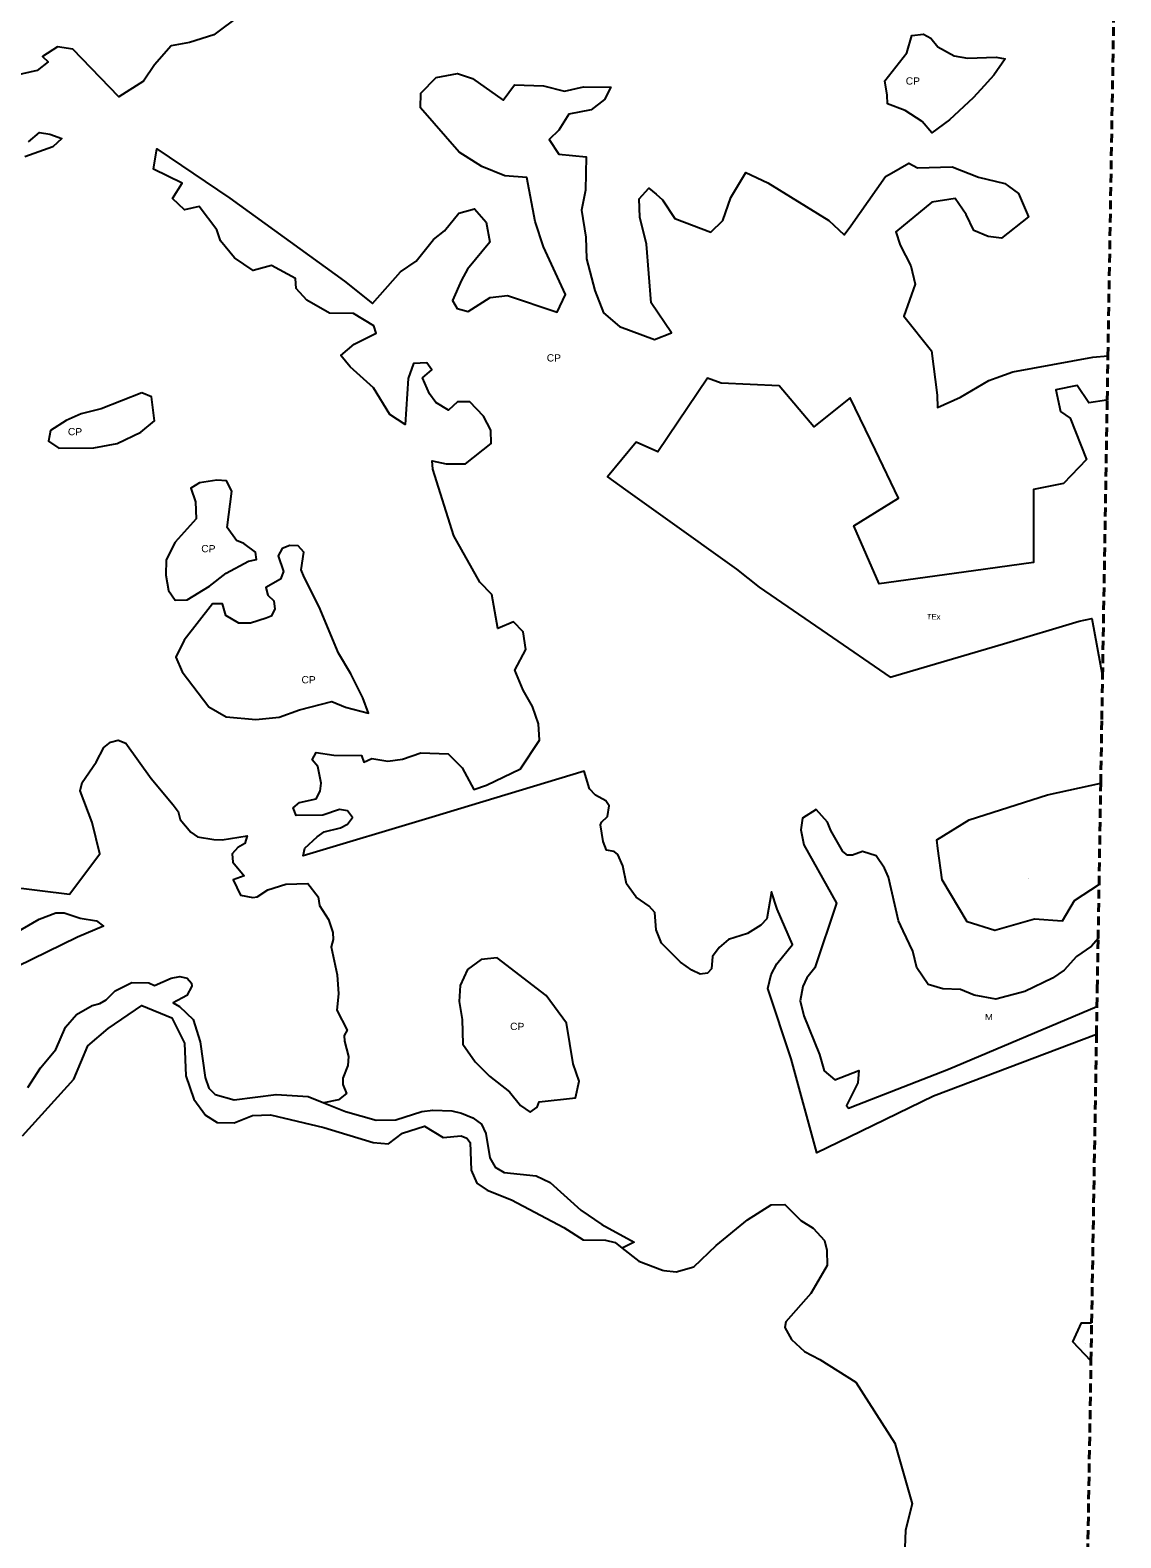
# Model space of a CAD drawing. Extents: x 713589 to 726391, y 7177764 to 7191819.
# Drawn here: x 725333 to 726289, y 7183880 to 7185202 of the extents above; entities that cross this region are included whole.
import ezdxf
from ezdxf.enums import TextEntityAlignment as Align

# ---------------------------------------------------------------- set-up
doc = ezdxf.new("R2010")
doc.units = 0
doc.header["$LTSCALE"] = 2.6
doc.linetypes.add('MEDIUM_DASHED', pattern=[4.5, 3, -1.5])
doc.layers.add('63', color=7, linetype='Continuous', lineweight=25)

msp = doc.modelspace()

# ---------------------------------------------------------------- linework, layer by layer
at = {"layer": '63', "linetype": 'MEDIUM_DASHED', "lineweight": 40}
for p, q in [((726277.23, 7184877.85), (726277.88, 7184916.55)), ((726273.14, 7184635.37), (726277.23, 7184877.85)), ((726270.06, 7184452.88), (726271.56, 7184541.89)), ((726269.26, 7184405.47), (726270.06, 7184452.88)), ((726267.84, 7184321.48), (726268.25, 7184346.03))]:
    msp.add_line(p, q, dxfattribs=at)
for points in [[(726277.88, 7184916.55), (726283.75, 7185264.1), (726286.04, 7185399.94), (726289.19, 7185586.4)], [(726271.56, 7184541.89), (726272.5, 7184597.61), (726273.14, 7184635.37)], [(726268.25, 7184346.03), (726268.51, 7184361.39), (726269.26, 7184405.47)], [(726263.01, 7184035.16), (726263.57, 7184068.5), (726267.84, 7184321.48)], [(726253.89, 7183494.95), (726256.31, 7183638.27), (726259.78, 7183843.69), (726263.01, 7184035.16)]]:
    msp.add_lwpolyline(points, dxfattribs=at)
at = {"layer": '63'}
for points in [[(725516.76, 7185215.41), (725493.64, 7185198.24), (725472.5, 7185191.64), (725456.32, 7185188.67), (725441.78, 7185171.84), (725432.2, 7185157.64), (725410.4, 7185143.77), (725370.12, 7185185.72), (725356.58, 7185187.71), (725343.48, 7185179.22), (725348.33, 7185174.58), (725338.7, 7185166.83), (725319.37, 7185162.58)], [(725718.19, 7184876.27), (725707.39, 7184876.27), (725699.52, 7184869.07), (725688.39, 7184875.62), (725682.83, 7184883.48), (725676.61, 7184897.24), (725684.8, 7184904.44), (725680.54, 7184910.66), (725668.75, 7184910.01), (725664.16, 7184896.91), (725661.53, 7184856.3), (725648.11, 7184865.15), (725633.7, 7184888.73), (725613.4, 7184907.08), (725605.22, 7184916.9), (725616.68, 7184927.05), (725636.01, 7184936.54), (725634.04, 7184943.1), (725616.36, 7184953.91), (725595.07, 7184954.24), (725575.43, 7184965.38), (725565.93, 7184975.86), (725565.28, 7184984.37), (725544.32, 7184995.84), (725528.27, 7184991.59), (725511.9, 7185002.72), (725499.46, 7185017.46), (725496.52, 7185027.29), (725480.8, 7185047.6), (725468.03, 7185044.65), (725457.55, 7185054.81), (725466.07, 7185068.23), (725440.85, 7185080.35), (725443.84, 7185098.36), (725507.7, 7185054.88), (725608.22, 7184982.16), (725633.01, 7184962.46), (725657.39, 7184990.29), (725671.27, 7184999.86), (725686.46, 7185018.68), (725696.04, 7185026.27), (725708.59, 7185041.79), (725722.46, 7185045.75), (725732.7, 7185033.86), (725735.67, 7185016.36), (725716.18, 7184992.58), (725710.89, 7184983.01), (725702.96, 7184965.18), (725707.25, 7184958.24), (725716.83, 7184955.6), (725735.99, 7184967.81), (725751.18, 7184969.46), (725794.77, 7184954.92), (725802.04, 7184970.44), (725782.89, 7185012.39), (725775.63, 7185034.51), (725768.37, 7185073.15), (725748.89, 7185074.48), (725728.75, 7185082.74), (725708.93, 7185095.29), (725674.93, 7185134.27), (725675.26, 7185147.15), (725688.8, 7185160.69), (725707.3, 7185164.31), (725720.51, 7185160.02), (725747.58, 7185140.86), (725757.49, 7185154.4), (725782.92, 7185153.4), (725801.41, 7185148.77), (725817.93, 7185152.73), (725842.04, 7185152.4), (725836.42, 7185141.5), (725824.53, 7185132.59), (725805.04, 7185128.63), (725796.45, 7185114.76), (725787.87, 7185106.5), (725796.45, 7185093.62), (725820.23, 7185091.31), (725819.56, 7185061.91), (725816.25, 7185044.41), (725819.88, 7185020.63), (725820.54, 7185001.81), (725827.8, 7184974.07), (725835.39, 7184954.25), (725849.59, 7184942.36), (725880.3, 7184931.12), (725895.16, 7184936.73), (725877.33, 7184963.16), (725873.05, 7185014.68), (725867.44, 7185038.46), (725866.88, 7185054.27), (725875.37, 7185063.88), (725881.6, 7185058.51), (725887.26, 7185053.64)], [(725331.15, 7185104.28), (725340.98, 7185112.47), (725349.82, 7185111.16), (725360.3, 7185107.23), (725352.44, 7185100.02), (725327.87, 7185091.19)], [(725887.26, 7185053.64), (725898.15, 7185037.13), (725929.52, 7185025.23), (725940.09, 7185035.47), (725947.03, 7185055.61), (725949.64, 7185059.91), (725960.25, 7185077.41), (725979.73, 7185068.48), (726033.22, 7185035.45), (726041.9, 7185027.2), (726046.43, 7185022.9), (726052.46, 7185030.76), (726082.84, 7185074.06), (726087.92, 7185076.94), (726103.25, 7185085.63), (726110.84, 7185081.67), (726141.22, 7185082.32), (726164.34, 7185073.4), (726187.45, 7185067.78), (726190.71, 7185065.43), (726199.34, 7185059.19), (726208.25, 7185038.71), (726184.47, 7185019.89), (726172.91, 7185021.22), (726160.37, 7185026.5), (726153.43, 7185040.71), (726143.86, 7185054.58), (726123.38, 7185051.61), (726091.72, 7185025.43), (726095.63, 7185013.84), (726104.88, 7184995.67), (726108.84, 7184979.49), (726098.92, 7184951.42), (726123.03, 7184921.03), (726127.97, 7184882.06), (726128.46, 7184871.32), (726148.45, 7184880.54), (726173.55, 7184895.06), (726179.94, 7184897.39), (726194.35, 7184902.65), (726264.51, 7184915.55), (726277.88, 7184916.55)], [(726277.23, 7184877.85), (726276.6, 7184877.76), (726261.15, 7184875.38), (726250.82, 7184890.67), (726232.21, 7184886.85), (726236.34, 7184867.74), (726244.61, 7184862), (726259.09, 7184825.7), (726238.99, 7184804.7), (726212.59, 7184799.48), (726212.66, 7184735.42), (726160.1, 7184728.12), (726077.24, 7184716.62), (726055.1, 7184767.57), (726094.33, 7184791.76), (726073.97, 7184834.03), (726051.91, 7184879.85), (726019.89, 7184854.49), (725989.41, 7184890.38), (725938.66, 7184892.56), (725926.63, 7184897.01), (725883.08, 7184832.57), (725864.13, 7184840.9), (725838.98, 7184810.68), (725854.78, 7184799.04), (725889.66, 7184774.28), (725952.05, 7184729.68), (725972.01, 7184713.87), (726031.63, 7184672.76), (726086.84, 7184634.68), (726186.16, 7184664.15), (726252.72, 7184683.91), (726263.76, 7184686.14), (726273.14, 7184635.37)], [(726267.84, 7184321.48), (726124.84, 7184267.37), (726050.81, 7184231.2), (726022.65, 7184217.44), (726000.05, 7184299.94), (725979.62, 7184361.66), (725982.63, 7184373.98), (725987.56, 7184383.29), (726001.16, 7184400.22), (725987.86, 7184431.43), (725982.68, 7184446.6), (725978.69, 7184422.86), (725973.56, 7184417.25), (725961.75, 7184410.05), (725945.22, 7184404.61), (725936.91, 7184397.71), (725931.13, 7184389.91), (725930.34, 7184379.04), (725926.57, 7184375.17), (725920.33, 7184374.34), (725912.89, 7184377.73), (725903.06, 7184384.91), (725886.31, 7184401.52), (725881.75, 7184413.3), (725880.59, 7184428.41), (725875.45, 7184433.96), (725864.07, 7184441.76), (725855.58, 7184453.59), (725852.38, 7184469.31), (725848.16, 7184479.12), (725844.88, 7184481.94), (725838, 7184483.13), (725835.05, 7184490.56), (725832.98, 7184505.28), (725833.61, 7184507.59), (725839.13, 7184512.56), (725840.46, 7184521.82), (725837.5, 7184526.42), (725828.48, 7184531.31), (725823.13, 7184536.96), (725818.65, 7184552.39), (725685.11, 7184512.14), (725572.21, 7184478.02), (725573.69, 7184484.95), (725584.5, 7184494.77), (725590.39, 7184499.03), (725604.8, 7184502.63), (725611.02, 7184505.9), (725615.28, 7184511.8), (725611.03, 7184517.69), (725603.82, 7184518.68), (725589.41, 7184513.77), (725565.83, 7184513.44), (725563.21, 7184520.32), (725568.78, 7184524.91), (725583.52, 7184528.18), (725587.12, 7184534.73), (725587.78, 7184541.93), (725584.84, 7184556.34), (725579.92, 7184562.24), (725583.53, 7184568.79), (725598.92, 7184566.49), (725623.23, 7184566.02), (725625.26, 7184560.27), (725632.32, 7184563.54), (725646.41, 7184561.24), (725659.18, 7184562.87), (725675.23, 7184568.44), (725699.13, 7184567.45), (725711.57, 7184555.33), (725721.72, 7184536.33), (725732.86, 7184539.93), (725762.66, 7184554.34), (725779.37, 7184579.55), (725778.39, 7184593.96), (725773.15, 7184609.03), (725764.97, 7184623.44), (725757.77, 7184640.8), (725767.27, 7184659.13), (725764.98, 7184674.53), (725756.47, 7184683.37), (725742.71, 7184677.48), (725737.48, 7184707.28), (725727, 7184718.09), (725704.09, 7184758.7), (725685.76, 7184817.33), (725685.11, 7184824.53), (725697.55, 7184821.91), (725714.58, 7184821.91), (725736.85, 7184839.91), (725736.53, 7184851.38), (725730.31, 7184863.82), (725718.19, 7184876.27)], [(725312.71, 7184451.3), (725367.08, 7184444.41), (725393.88, 7184479.89), (725387.02, 7184507.26), (725376.55, 7184535.1), (725378.19, 7184542.3), (725390.64, 7184560.31), (725397.19, 7184573.08), (725403.08, 7184577.67), (725409.96, 7184579.63), (725416.51, 7184577.01), (725438.77, 7184545.89), (725458.09, 7184522.96), (725462.35, 7184517.07), (725464.31, 7184509.86), (725473.48, 7184498.73), (725479.37, 7184494.8), (725493.78, 7184492.5), (725500.99, 7184492.17), (725522.93, 7184495.77), (725520.96, 7184488.89), (725514.74, 7184485.29), (725509.82, 7184479.72), (725510.48, 7184472.52), (725520.31, 7184460.4), (725510.71, 7184457.14), (725517.12, 7184443.66), (725527.98, 7184441.39), (725531.86, 7184442.02), (725541.12, 7184448.12), (725556.79, 7184453.29), (725576.24, 7184453.69), (725585.18, 7184442.06), (725586.56, 7184434.58), (725594.37, 7184422.11), (725598.08, 7184410.93), (725598.44, 7184404.64), (725596.67, 7184398.19), (725601.9, 7184373.65), (725603.14, 7184357.13), (725601.69, 7184342.6), (725610.81, 7184325.25), (725608.16, 7184320.51), (725608.23, 7184315.42), (725611.82, 7184302.11), (725611.22, 7184294.1), (725607.02, 7184283.07), (725606.96, 7184277.6), (725610.15, 7184269.57), (725603, 7184263.98), (725590.34, 7184261.41)], [(726270.06, 7184452.88), (726248.39, 7184438.74), (726237.66, 7184420.68), (726213.61, 7184422.64), (726178.55, 7184412.62), (726154.5, 7184420.32), (726132.42, 7184457.15), (726128.78, 7184484.6), (726127.76, 7184492.26), (726156.23, 7184509.52), (726224.87, 7184531.72), (726271.56, 7184541.89)], [(726269.26, 7184405.47), (726263.36, 7184398.88), (726250.23, 7184389.72), (726239.35, 7184377.75), (726229.17, 7184370.8), (726204.91, 7184358.99), (726179.63, 7184352.33), (726160.48, 7184355.79), (726148.45, 7184360.84), (726133.14, 7184361.38), (726120.21, 7184365.22), (726110.24, 7184379.89), (726106.87, 7184394.59), (726098.37, 7184412.2), (726094.15, 7184420.96), (726085.57, 7184459.35), (726081.93, 7184467.14), (726074.68, 7184478.22), (726062.64, 7184481.84), (726053.96, 7184478.73), (726049.35, 7184478.77), (726045.36, 7184481.84), (726034.73, 7184500.27), (726032.07, 7184507.65), (726022.1, 7184518.7), (726009.98, 7184511.26), (726008.53, 7184500.75), (726011.29, 7184487.85), (726039.76, 7184436.66), (726020.76, 7184379.8), (726013.9, 7184371.07), (726010.33, 7184363.54), (726007.98, 7184350.92), (726011.04, 7184337.73), (726025, 7184303.86), (726028.97, 7184289.46), (726038.31, 7184281.7), (726059.29, 7184289.9), (726058.44, 7184279.09), (726048.62, 7184258.93), (726050.43, 7184256.83), (726058.58, 7184260), (726137.95, 7184290.84), (726268.25, 7184346.03)], [(725307.75, 7184403.46), (725340.5, 7184422.45), (725355.24, 7184428.01), (725362.44, 7184428.01), (725376.52, 7184423.43), (725390.93, 7184421.13), (725396.86, 7184416.51), (725374.2, 7184406.71), (725281.28, 7184361.43)], [(725330.56, 7184274.75), (725341.75, 7184292.12), (725355.23, 7184308.11), (725363.54, 7184327.92), (725373.24, 7184339.03), (725387.04, 7184346.93), (725393.83, 7184348.54), (725399.32, 7184351.72), (725407.28, 7184359.63), (725421.78, 7184366.88), (725436.86, 7184366.78), (725441.83, 7184364.44), (725456.42, 7184370.86), (725463.91, 7184372.29), (725470.49, 7184370.71), (725474.21, 7184366.33), (725474.46, 7184363.7), (725470.11, 7184355.71), (725458.2, 7184349.16), (725463.77, 7184345.85), (725475.48, 7184334.48), (725481.86, 7184315), (725486.18, 7184283.76), (725489.47, 7184274.24), (725494.9, 7184268.8), (725511.44, 7184264.02), (725548.32, 7184268.79), (725576.37, 7184266.99), (725590.34, 7184261.41)], [(725325.86, 7184232.47), (725371.06, 7184282.09), (725383.17, 7184311.44), (725401.22, 7184326.6), (725430.67, 7184346.84), (725456.95, 7184336.11), (725467.95, 7184313.86), (725469.22, 7184285.13), (725476.31, 7184264.53), (725486.42, 7184250.64), (725496.78, 7184244.28), (725511.56, 7184243.81), (725527.71, 7184250.31), (725543.32, 7184250.95), (725590.24, 7184239.77), (725633.55, 7184226.62), (725646.94, 7184225.58), (725659.16, 7184234.85), (725678.37, 7184241.09), (725694.89, 7184230.86), (725710.78, 7184232.34), (725715.53, 7184230.42), (725718.62, 7184226.53), (725719.31, 7184202.27), (725724.39, 7184190.86), (725733.35, 7184184.77), (725754.87, 7184176.24), (725800.75, 7184151.95), (725817.54, 7184141.16), (725837.35, 7184140.99), (725845.73, 7184138.8), (725851.85, 7184133.98)], [(725590.34, 7184261.41), (725609.35, 7184253.83), (725636.16, 7184246.15), (725653.25, 7184246.55), (725676.13, 7184253.67), (725685.74, 7184254.91), (725702.59, 7184254.26), (725710.86, 7184252.36), (725720.92, 7184248.33), (725728.59, 7184242.74), (725732.28, 7184234.62), (725735.81, 7184213.29), (725740.49, 7184205.07), (725748.47, 7184200.28), (725776.3, 7184197.24), (725788.6, 7184191.44), (725815.72, 7184167.23), (725834.09, 7184154.7), (725862.35, 7184139.11), (725851.85, 7184133.98)], [(725851.85, 7184133.98), (725866.46, 7184122.46), (725887.14, 7184114.49), (725888.38, 7184114.35), (725899.14, 7184113.16), (725914.74, 7184117.7), (725934.16, 7184136.22), (725961.65, 7184158.68), (725982.5, 7184171.91), (725994.49, 7184172.25), (726008.51, 7184158.1), (726019.43, 7184151.47), (726029.25, 7184140.64), (726031.25, 7184132.29), (726031.6, 7184118.62), (726017.23, 7184094.28), (725995.32, 7184069.45), (725994.52, 7184064.31), (726000.44, 7184053.74), (726011.65, 7184043.2), (726025.35, 7184036.31), (726056.7, 7184016.39), (726091.02, 7183962.75), (726106.1, 7183909.56), (726100.37, 7183886.66), (726099.61, 7183871.03)], [(726263.01, 7184035.16), (726247.08, 7184051.72), (726254.81, 7184068.57), (726263.57, 7184068.5)]]:
    msp.add_lwpolyline(points, dxfattribs=at)
for points in [[(726177.9, 7185162.89), (726166.34, 7185150.28), (726159.73, 7185143.08), (726138.92, 7185123.6), (726123.4, 7185112.38), (726114.81, 7185122.29), (726099.95, 7185131.87), (726084.51, 7185137.81), (726084.17, 7185145.42), (726082.2, 7185157.96), (726101.62, 7185182.39), (726105.91, 7185197.58), (726116.15, 7185198.9), (726122.42, 7185195.27), (726128.7, 7185187.67), (726142.9, 7185179.74), (726154.78, 7185177.76), (726179.88, 7185178.74), (726187.81, 7185177.09)], [(725430.66, 7184884.19), (725394.96, 7184870.12), (725377.27, 7184865.86), (725364.17, 7184859.97), (725350.42, 7184851.13), (725348.78, 7184841.96), (725357.95, 7184835.75), (725388.4, 7184836.06), (725409.04, 7184839.66), (725429.67, 7184849.8), (725441.79, 7184859.63), (725439.17, 7184880.59)], [(725459.78, 7184753.19), (725451.91, 7184737.8), (725451.58, 7184724.37), (725453.87, 7184710.94), (725459.77, 7184702.43), (725470.25, 7184702.75), (725489.9, 7184714.54), (725504.64, 7184726), (725524.29, 7184736.47), (725531.17, 7184738.11), (725530.17, 7184744.35), (725520.04, 7184752.19), (725513.49, 7184754.81), (725505.3, 7184765.95), (725509.57, 7184798.04), (725504.98, 7184806.89), (725496.47, 7184807.54), (725481.08, 7184805.26), (725473.54, 7184800.67), (725477.8, 7184788.55), (725478.12, 7184773.82)], [(725525.92, 7184682.11), (725515.76, 7184682.11), (725504.3, 7184688.99), (725501.36, 7184699.14), (725492.51, 7184699.15), (725467.62, 7184667.39), (725460.41, 7184652.32), (725465.98, 7184639.55), (725489.22, 7184608.76), (725504.61, 7184599.91), (725530.48, 7184597.62), (725551.11, 7184599.58), (725568.8, 7184606.12), (725597.29, 7184613.32), (725609.08, 7184608.41), (725629.28, 7184603.36), (725624.32, 7184616.74), (725613.78, 7184637.83), (725603.2, 7184655.89), (725586.18, 7184696.51), (725573.08, 7184722.38), (725570.46, 7184728.93), (725572.76, 7184744.32), (725567.85, 7184749.89), (725560.32, 7184750.22), (725553.77, 7184747.6), (725550.16, 7184741.38), (725554.74, 7184727.62), (725552.12, 7184720.75), (725539.35, 7184713.55), (725540.98, 7184706.67), (725546.22, 7184701.75), (725547.2, 7184694.55), (725543.93, 7184688.33), (725539.75, 7184686.66)], [(725722.95, 7184297.45), (725735.54, 7184284.85), (725753.07, 7184271.15), (725762.65, 7184259.1), (725771.14, 7184253.34), (725777.17, 7184257.72), (725779.09, 7184262.38), (725810.86, 7184265.66), (725814.15, 7184280.45), (725808.95, 7184295.51), (725802.93, 7184331.4), (725785.13, 7184355.5), (725742.14, 7184388.65), (725728.17, 7184387.29), (725716.12, 7184378.25), (725709.81, 7184364.28), (725708.99, 7184350.32), (725711.45, 7184334.43), (725711.99, 7184312.79)]]:
    msp.add_lwpolyline(points, close=True, dxfattribs=at)

# ---------------------------------------------------------------- texts
for s, height, width, p in [('CP', 6.4, 1.05, (726106.74, 7185154.57)), ('CP', 6.4, 1.05, (725791.92, 7184911.66)), ('CP', 6.4, 1.05, (725371.94, 7184846.95)), ('CP', 6.4, 1.05, (725488.91, 7184744.33)), ('TEx', 4.8, 1.05, (726124.97, 7184685.43)), ('CP', 6.4, 1.05, (725576.8, 7184629.36)), ('M', 0.52, 1.2, (726208.39, 7184457.97)), ('CP', 6.4, 1.05, (725759.78, 7184325.24)), ('M', 5.2, 1.2, (726173.43, 7184334.11)), ('CP', 0.32, 1.05, (726258.74, 7184050.12))]:
    msp.add_text(s, height=height, rotation=359.062, dxfattribs=dict(at, width=width)).set_placement(p, align=Align.CENTER)

doc.saveas('drawing.dxf')
